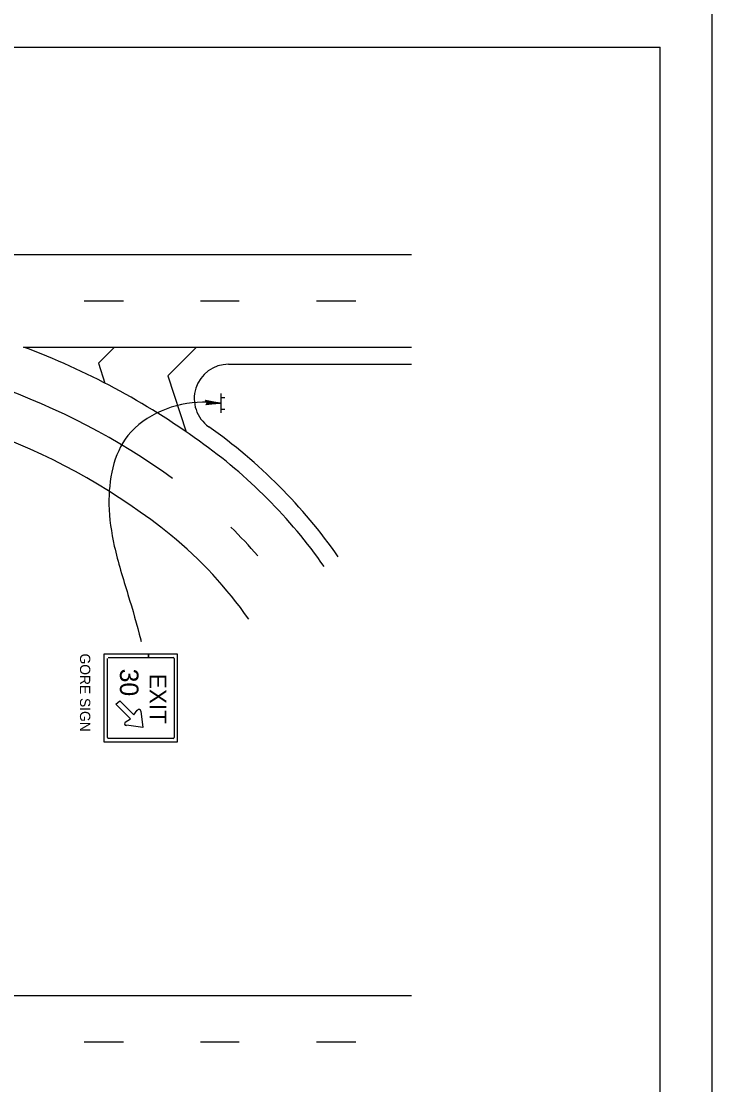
# Model space of a CAD drawing. Extents: x 644898 to 648326, y 298294 to 300670.
# Drawn here: x 645538.5 to 645739.3, y 298571.8 to 298881 of the extents above; entities that cross this region are included whole.
import ezdxf

# ---------------------------------------------------------------- set-up
doc = ezdxf.new("R2010")
doc.units = 0
for name, color, linetype in [('1', 7, 'Continuous'), ('2', 7, 'Continuous'), ('XCS-GRID-MIN', 7, 'Continuous')]:
    doc.layers.add(name, color=color, linetype=linetype)

msp = doc.modelspace()

# ---------------------------------------------------------------- linework, layer by layer
at = {"layer": '1'}
for p in [(644938.32, 298873.49), (645724.32, 298309.49)]:
    msp.add_line(p, (645724.32, 298873.49), dxfattribs=at)
at = {"layer": '2'}
for p, q in [((645010.69, 298813.15), (645651.96, 298813.15)), ((645556.78, 298799.69), (645568.28, 298799.69)), ((645590.66, 298799.69), (645601.91, 298799.69)), ((645624.41, 298799.69), (645635.78, 298799.69)), ((645539.18, 298786.27), (645598.81, 298786.27)), ((645565.62, 298786.27), (645560.93, 298781.58)), ((645589.44, 298786.27), (645581.09, 298777.93)), ((645598.81, 298786.27), (645651.96, 298786.27)), ((645560.93, 298781.58), (645562.85, 298775.79)), ((645598.81, 298781.27), (645651.96, 298781.27)), ((645581.09, 298777.93), (645586.5, 298761.6)), ((645596.63, 298767.14), (645596.63, 298772.76)), ((645596.63, 298771.64), (645597.75, 298771.64)), ((645596.63, 298768.26), (645597.75, 298768.26)), ((645575.53, 298696.98), (645562.57, 298696.98)), ((645562.57, 298696.98), (645562.57, 298671.47)), ((645563.57, 298672.72), (645563.57, 298695.73)), ((645563.82, 298695.98), (645575.53, 298695.98)), ((645575.53, 298695.98), (645575.53, 298696.98)), ((645583.95, 298696.98), (645575.53, 298696.98)), ((645575.53, 298696.98), (645575.53, 298695.98)), ((645575.53, 298695.98), (645582.7, 298695.98)), ((645582.95, 298695.73), (645582.95, 298672.72)), ((645583.95, 298671.47), (645583.95, 298696.98)), ((645566.01, 298682.44), (645567.14, 298683.44)), ((645567.14, 298683.44), (645571.26, 298679.32)), ((645570.26, 298678.19), (645566.01, 298682.44)), ((645571.26, 298679.32), (645572.26, 298680.69)), ((645573.26, 298680.44), (645573.89, 298675.69)), ((645568.76, 298677.19), (645570.26, 298678.19)), ((645573.89, 298675.69), (645569.14, 298676.32)), ((645562.57, 298671.47), (645583.95, 298671.47)), ((645582.7, 298672.47), (645563.82, 298672.47)), ((645010.69, 298597.76), (645651.96, 298597.76)), ((645556.78, 298584.3), (645568.28, 298584.3)), ((645590.66, 298584.3), (645601.91, 298584.3)), ((645624.41, 298584.3), (645635.78, 298584.3))]:
    msp.add_line(p, q, dxfattribs=at)
msp.add_lwpolyline([(645592.33, 298770.58), (645592.44, 298770.44), (645596.42, 298769.96), (645592.33, 298770.58), (645592.12, 298770.86), (645596.42, 298769.96), (645592.51, 298769.93), (645592.35, 298769.7), (645596.42, 298769.96), (645592.2, 298769.46), (645592.35, 298769.7)], dxfattribs=at)
for centre, radius, start, end in [((645463.66, 298583.71), 202.81, 54.115, 87.1891), ((645463.66, 298583.71), 216.18, 54.1362, 69.554), ((645598.81, 298771.27), 10, 90, 234.8419), ((645463.66, 298583.71), 189.43, 51.3209, 87.1047), ((645504.05, 298636.73), 154.56, 34.9711, 54.8419), ((645504.05, 298636.73), 149.56, 34.9711, 54.7736), ((645504.05, 298636.73), 136.19, 40.6935, 45.5167), ((645504.05, 298636.73), 122.81, 34.9711, 50.5694), ((645582.7, 298695.73), 0.25, 360, 90), ((645572.72, 298680.32), 0.559, 4.8591, 145.5247), ((645569.12, 298676.77), 0.559, 123.2476, 267.1542), ((645563.82, 298672.72), 0.25, 180, 270)]:
    msp.add_arc(centre, radius, start, end, dxfattribs=at)
msp.add_ellipse((645582.7, 298672.72), major_axis=(0.25, 0), ratio=0.999585, start_param=4.712389, end_param=6.283185, dxfattribs=at)
msp.add_spline([(645596.04, 298769.99), (645591.21, 298770.22), (645569.53, 298760.54), (645564.02, 298740.52), (645565.57, 298728.42), (645569.53, 298714.34), (645573.27, 298701.14), (645573.38, 298700.7)], degree=3, dxfattribs=at)
at = {"layer": 'XCS-GRID-MIN'}
msp.add_lwpolyline([(644898.32, 298888.49), (645739.32, 298888.49), (645739.32, 298294.49), (644898.32, 298294.49)], close=True, dxfattribs=at)

# ---------------------------------------------------------------- texts
at = {"layer": '2'}
for s, height, p in [('GORE SIGN', 3, (645555.58, 298697.16)), ('30', 5.375, (645567.21, 298692.76)), ('EXIT', 4.917, (645575.81, 298691.29))]:
    msp.add_text(s, height=height, rotation=270, dxfattribs=at).set_placement(p)

doc.saveas('drawing.dxf')
